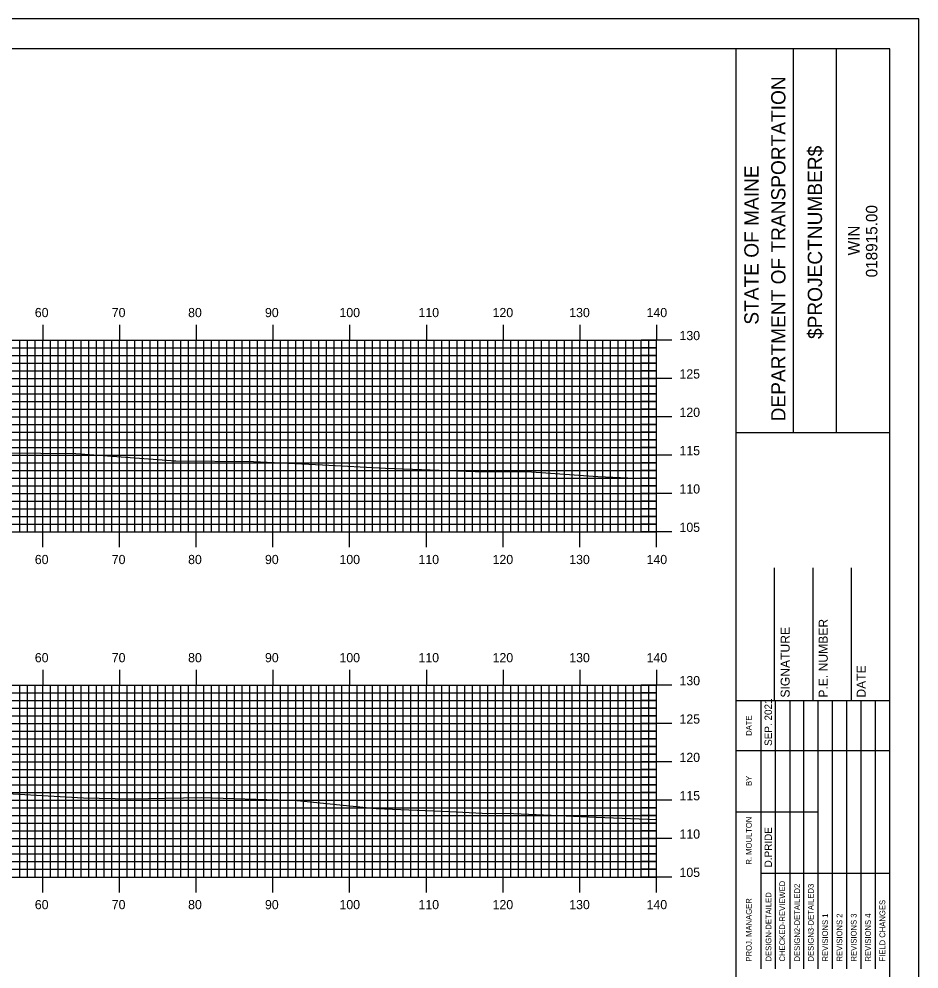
# Model space of a CAD drawing. Extents: x 1771629 to 1771972, y 442591 to 442811.
# Drawn here: x 1771851.5 to 1771968.8, y 442686.7 to 442810.5 of the extents above; entities that cross this region are included whole.
import ezdxf

# ---------------------------------------------------------------- set-up
doc = ezdxf.new("R2010")
doc.units = 0
for name, color, linetype in [('BORDER', 7, 'Continuous'), ('H_V ANNOTATION', 7, 'Continuous'), ('MAJOR', 7, 'Continuous'), ('MINOR', 7, 'Continuous'), ('PLOT BOUNDARY', 7, 'Continuous'), ('S_Roadway_Centerline', 7, 'Continuous')]:
    doc.layers.add(name, color=color, linetype=linetype)

msp = doc.modelspace()

# ---------------------------------------------------------------- linework, layer by layer
at = {"layer": 'BORDER'}
for p, q in [((1771944.98, 442596.67), (1771944.98, 442806.67)), ((1771952.44, 442756.66), (1771952.44, 442806.66)), ((1771958.03, 442756.66), (1771958.03, 442806.66)), ((1771944.98, 442756.65), (1771964.98, 442756.65)), ((1771949.98, 442721.67), (1771949.98, 442738.97)), ((1771954.98, 442721.67), (1771954.98, 442738.97)), ((1771959.98, 442721.67), (1771959.98, 442738.97)), ((1771944.98, 442721.67), (1771964.98, 442721.67))]:
    msp.add_line(p, q, dxfattribs=at)
msp.add_lwpolyline([(1771644.98, 442596.67), (1771964.98, 442596.67), (1771964.98, 442806.67), (1771644.98, 442806.67)], close=True, dxfattribs=at)
for points in [[(1771948.21, 442715.17), (1771948.21, 442721.67)], [(1771950.08, 442686.68), (1771950.08, 442721.67)], [(1771951.94, 442721.67), (1771951.94, 442686.68)], [(1771953.8, 442686.68), (1771953.8, 442721.67)], [(1771955.67, 442686.68), (1771955.67, 442721.67)], [(1771957.53, 442686.68), (1771957.53, 442721.67)], [(1771959.39, 442686.68), (1771959.39, 442721.67)], [(1771961.26, 442686.68), (1771961.26, 442721.67)], [(1771963.12, 442686.68), (1771963.12, 442721.67)], [(1771948.21, 442686.68), (1771948.21, 442720.26)], [(1771944.98, 442715.17), (1771964.98, 442715.17)], [(1771944.98, 442707.17), (1771948.21, 442707.17)], [(1771948.21, 442707.17), (1771955.66, 442707.17)], [(1771948.21, 442699.17), (1771964.98, 442699.17)]]:
    msp.add_lwpolyline(points, dxfattribs=at)
at = {"layer": 'MAJOR'}
for p, q in [((1771854.58, 442770.67), (1771854.58, 442768.67)), ((1771864.58, 442770.67), (1771864.58, 442768.67)), ((1771874.58, 442770.67), (1771874.58, 442768.67)), ((1771884.58, 442770.67), (1771884.58, 442768.67)), ((1771894.58, 442770.67), (1771894.58, 442768.67)), ((1771904.58, 442770.67), (1771904.58, 442768.67)), ((1771914.58, 442770.67), (1771914.58, 442768.67)), ((1771924.58, 442770.67), (1771924.58, 442768.67)), ((1771934.58, 442770.67), (1771934.58, 442768.67)), ((1771654.58, 442768.67), (1771934.58, 442768.67)), ((1771654.58, 442768.67), (1771934.58, 442768.67)), ((1771854.58, 442743.67), (1771854.58, 442768.67)), ((1771864.58, 442743.67), (1771864.58, 442768.67)), ((1771874.58, 442743.67), (1771874.58, 442768.67)), ((1771884.58, 442743.67), (1771884.58, 442768.67)), ((1771894.58, 442743.67), (1771894.58, 442768.67)), ((1771904.58, 442743.67), (1771904.58, 442768.67)), ((1771914.58, 442743.67), (1771914.58, 442768.67)), ((1771924.58, 442743.67), (1771924.58, 442768.67)), ((1771936.58, 442768.67), (1771932.58, 442768.67)), ((1771934.58, 442743.67), (1771934.58, 442768.67)), ((1771934.58, 442743.67), (1771934.58, 442768.67)), ((1771654.58, 442763.67), (1771934.58, 442763.67)), ((1771936.58, 442763.67), (1771932.58, 442763.67)), ((1771654.58, 442758.67), (1771934.58, 442758.67)), ((1771936.58, 442758.67), (1771932.58, 442758.67)), ((1771654.58, 442753.67), (1771934.58, 442753.67)), ((1771936.58, 442753.67), (1771932.58, 442753.67)), ((1771654.58, 442748.67), (1771934.58, 442748.67)), ((1771936.58, 442748.67), (1771932.58, 442748.67)), ((1771654.58, 442743.67), (1771934.58, 442743.67)), ((1771654.58, 442743.67), (1771934.58, 442743.67)), ((1771854.58, 442741.66), (1771854.58, 442743.67)), ((1771864.58, 442741.66), (1771864.58, 442743.67)), ((1771874.58, 442741.66), (1771874.58, 442743.67)), ((1771884.58, 442741.66), (1771884.58, 442743.67)), ((1771894.58, 442741.66), (1771894.58, 442743.67)), ((1771904.58, 442741.66), (1771904.58, 442743.67)), ((1771914.58, 442741.66), (1771914.58, 442743.67)), ((1771924.58, 442741.66), (1771924.58, 442743.67)), ((1771936.58, 442743.67), (1771932.58, 442743.67)), ((1771934.58, 442741.66), (1771934.58, 442743.67)), ((1771854.58, 442725.67), (1771854.58, 442723.67)), ((1771864.58, 442725.67), (1771864.58, 442723.67)), ((1771874.58, 442725.67), (1771874.58, 442723.67)), ((1771884.58, 442725.67), (1771884.58, 442723.67)), ((1771894.58, 442725.67), (1771894.58, 442723.67)), ((1771904.58, 442725.67), (1771904.58, 442723.67)), ((1771914.58, 442725.67), (1771914.58, 442723.67)), ((1771924.58, 442725.67), (1771924.58, 442723.67)), ((1771934.58, 442725.67), (1771934.58, 442723.67)), ((1771654.58, 442723.67), (1771934.58, 442723.67)), ((1771654.58, 442723.67), (1771934.58, 442723.67)), ((1771854.58, 442698.67), (1771854.58, 442723.67)), ((1771864.58, 442698.67), (1771864.58, 442723.67)), ((1771874.58, 442698.67), (1771874.58, 442723.67)), ((1771884.58, 442698.67), (1771884.58, 442723.67)), ((1771894.58, 442698.67), (1771894.58, 442723.67)), ((1771904.58, 442698.67), (1771904.58, 442723.67)), ((1771914.58, 442698.67), (1771914.58, 442723.67)), ((1771924.58, 442698.67), (1771924.58, 442723.67)), ((1771936.58, 442723.67), (1771932.58, 442723.67)), ((1771934.58, 442698.67), (1771934.58, 442723.67)), ((1771934.58, 442698.67), (1771934.58, 442723.67)), ((1771654.58, 442718.67), (1771934.58, 442718.67)), ((1771936.58, 442718.67), (1771932.58, 442718.67)), ((1771654.58, 442713.67), (1771934.58, 442713.67)), ((1771936.58, 442713.67), (1771932.58, 442713.67)), ((1771654.58, 442708.67), (1771934.58, 442708.67)), ((1771936.58, 442708.67), (1771932.58, 442708.67)), ((1771654.58, 442703.67), (1771934.58, 442703.67)), ((1771936.58, 442703.67), (1771932.58, 442703.67)), ((1771654.58, 442698.67), (1771934.58, 442698.67)), ((1771654.58, 442698.67), (1771934.58, 442698.67)), ((1771854.58, 442696.66), (1771854.58, 442698.67)), ((1771864.58, 442696.66), (1771864.58, 442698.67)), ((1771874.58, 442696.66), (1771874.58, 442698.67)), ((1771884.58, 442696.66), (1771884.58, 442698.67)), ((1771894.58, 442696.66), (1771894.58, 442698.67)), ((1771904.58, 442696.66), (1771904.58, 442698.67)), ((1771914.58, 442696.66), (1771914.58, 442698.67)), ((1771924.58, 442696.66), (1771924.58, 442698.67)), ((1771936.58, 442698.67), (1771932.58, 442698.67)), ((1771934.58, 442696.66), (1771934.58, 442698.67))]:
    msp.add_line(p, q, dxfattribs=at)
at = {"layer": 'MINOR'}
for p, q in [((1771851.58, 442743.67), (1771851.58, 442768.67)), ((1771852.58, 442743.67), (1771852.58, 442768.67)), ((1771853.58, 442743.67), (1771853.58, 442768.67)), ((1771855.58, 442743.67), (1771855.58, 442768.67)), ((1771856.58, 442743.67), (1771856.58, 442768.67)), ((1771857.58, 442743.67), (1771857.58, 442768.67)), ((1771858.58, 442743.67), (1771858.58, 442768.67)), ((1771859.58, 442743.67), (1771859.58, 442768.67)), ((1771860.58, 442743.67), (1771860.58, 442768.67)), ((1771861.58, 442743.67), (1771861.58, 442768.67)), ((1771862.58, 442743.67), (1771862.58, 442768.67)), ((1771863.58, 442743.67), (1771863.58, 442768.67)), ((1771865.58, 442743.67), (1771865.58, 442768.67)), ((1771866.58, 442743.67), (1771866.58, 442768.67)), ((1771867.58, 442743.67), (1771867.58, 442768.67)), ((1771868.58, 442743.67), (1771868.58, 442768.67)), ((1771869.58, 442743.67), (1771869.58, 442768.67)), ((1771870.58, 442743.67), (1771870.58, 442768.67)), ((1771871.58, 442743.67), (1771871.58, 442768.67)), ((1771872.58, 442743.67), (1771872.58, 442768.67)), ((1771873.58, 442743.67), (1771873.58, 442768.67)), ((1771875.58, 442743.67), (1771875.58, 442768.67)), ((1771876.58, 442743.67), (1771876.58, 442768.67)), ((1771877.58, 442743.67), (1771877.58, 442768.67)), ((1771878.58, 442743.67), (1771878.58, 442768.67)), ((1771879.58, 442743.67), (1771879.58, 442768.67)), ((1771880.58, 442743.67), (1771880.58, 442768.67)), ((1771881.58, 442743.67), (1771881.58, 442768.67)), ((1771882.58, 442743.67), (1771882.58, 442768.67)), ((1771883.58, 442743.67), (1771883.58, 442768.67)), ((1771885.58, 442743.67), (1771885.58, 442768.67)), ((1771886.58, 442743.67), (1771886.58, 442768.67)), ((1771887.58, 442743.67), (1771887.58, 442768.67)), ((1771888.58, 442743.67), (1771888.58, 442768.67)), ((1771889.58, 442743.67), (1771889.58, 442768.67)), ((1771890.58, 442743.67), (1771890.58, 442768.67)), ((1771891.58, 442743.67), (1771891.58, 442768.67)), ((1771892.58, 442743.67), (1771892.58, 442768.67)), ((1771893.58, 442743.67), (1771893.58, 442768.67)), ((1771895.58, 442743.67), (1771895.58, 442768.67)), ((1771896.58, 442743.67), (1771896.58, 442768.67)), ((1771897.58, 442743.67), (1771897.58, 442768.67)), ((1771898.58, 442743.67), (1771898.58, 442768.67)), ((1771899.58, 442743.67), (1771899.58, 442768.67)), ((1771900.58, 442743.67), (1771900.58, 442768.67)), ((1771901.58, 442743.67), (1771901.58, 442768.67)), ((1771902.58, 442743.67), (1771902.58, 442768.67)), ((1771903.58, 442743.67), (1771903.58, 442768.67)), ((1771905.58, 442743.67), (1771905.58, 442768.67)), ((1771906.58, 442743.67), (1771906.58, 442768.67)), ((1771907.58, 442743.67), (1771907.58, 442768.67)), ((1771908.58, 442743.67), (1771908.58, 442768.67)), ((1771909.58, 442743.67), (1771909.58, 442768.67)), ((1771910.58, 442743.67), (1771910.58, 442768.67)), ((1771911.58, 442743.67), (1771911.58, 442768.67)), ((1771912.58, 442743.67), (1771912.58, 442768.67)), ((1771913.58, 442743.67), (1771913.58, 442768.67)), ((1771915.58, 442743.67), (1771915.58, 442768.67)), ((1771916.58, 442743.67), (1771916.58, 442768.67)), ((1771917.58, 442743.67), (1771917.58, 442768.67)), ((1771918.58, 442743.67), (1771918.58, 442768.67)), ((1771919.58, 442743.67), (1771919.58, 442768.67)), ((1771920.58, 442743.67), (1771920.58, 442768.67)), ((1771921.58, 442743.67), (1771921.58, 442768.67)), ((1771922.58, 442743.67), (1771922.58, 442768.67)), ((1771923.58, 442743.67), (1771923.58, 442768.67)), ((1771925.58, 442743.67), (1771925.58, 442768.67)), ((1771926.58, 442743.67), (1771926.58, 442768.67)), ((1771927.58, 442743.67), (1771927.58, 442768.67)), ((1771928.58, 442743.67), (1771928.58, 442768.67)), ((1771929.58, 442743.67), (1771929.58, 442768.67)), ((1771930.58, 442743.67), (1771930.58, 442768.67)), ((1771931.58, 442743.67), (1771931.58, 442768.67)), ((1771932.58, 442743.67), (1771932.58, 442768.67)), ((1771933.58, 442743.67), (1771933.58, 442768.67)), ((1771654.58, 442767.67), (1771934.58, 442767.67)), ((1771934.58, 442767.67), (1771932.58, 442767.67)), ((1771654.58, 442766.67), (1771934.58, 442766.67)), ((1771934.58, 442766.67), (1771932.58, 442766.67)), ((1771654.58, 442765.67), (1771934.58, 442765.67)), ((1771934.58, 442765.67), (1771932.58, 442765.67)), ((1771654.58, 442764.67), (1771934.58, 442764.67)), ((1771934.58, 442764.67), (1771932.58, 442764.67)), ((1771654.58, 442762.67), (1771934.58, 442762.67)), ((1771934.58, 442762.67), (1771932.58, 442762.67)), ((1771654.58, 442761.67), (1771934.58, 442761.67)), ((1771934.58, 442761.67), (1771932.58, 442761.67)), ((1771654.58, 442760.67), (1771934.58, 442760.67)), ((1771934.58, 442760.67), (1771932.58, 442760.67)), ((1771654.58, 442759.67), (1771934.58, 442759.67)), ((1771934.58, 442759.67), (1771932.58, 442759.67)), ((1771654.58, 442757.67), (1771934.58, 442757.67)), ((1771934.58, 442757.67), (1771932.58, 442757.67)), ((1771654.58, 442756.67), (1771934.58, 442756.67)), ((1771934.58, 442756.67), (1771932.58, 442756.67)), ((1771654.58, 442755.67), (1771934.58, 442755.67)), ((1771934.58, 442755.67), (1771932.58, 442755.67)), ((1771654.58, 442754.67), (1771934.58, 442754.67)), ((1771934.58, 442754.67), (1771932.58, 442754.67)), ((1771654.58, 442752.67), (1771934.58, 442752.67)), ((1771934.58, 442752.67), (1771932.58, 442752.67)), ((1771654.58, 442751.67), (1771934.58, 442751.67)), ((1771934.58, 442751.67), (1771932.58, 442751.67)), ((1771654.58, 442750.67), (1771934.58, 442750.67)), ((1771934.58, 442750.67), (1771932.58, 442750.67)), ((1771654.58, 442749.67), (1771934.58, 442749.67)), ((1771934.58, 442749.67), (1771932.58, 442749.67)), ((1771654.58, 442747.67), (1771934.58, 442747.67)), ((1771934.58, 442747.67), (1771932.58, 442747.67)), ((1771654.58, 442746.67), (1771934.58, 442746.67)), ((1771934.58, 442746.67), (1771932.58, 442746.67)), ((1771654.58, 442745.67), (1771934.58, 442745.67)), ((1771934.58, 442745.67), (1771932.58, 442745.67)), ((1771654.58, 442744.67), (1771934.58, 442744.67)), ((1771934.58, 442744.67), (1771932.58, 442744.67)), ((1771851.58, 442698.67), (1771851.58, 442723.67)), ((1771852.58, 442698.67), (1771852.58, 442723.67)), ((1771853.58, 442698.67), (1771853.58, 442723.67)), ((1771855.58, 442698.67), (1771855.58, 442723.67)), ((1771856.58, 442698.67), (1771856.58, 442723.67)), ((1771857.58, 442698.67), (1771857.58, 442723.67)), ((1771858.58, 442698.67), (1771858.58, 442723.67)), ((1771859.58, 442698.67), (1771859.58, 442723.67)), ((1771860.58, 442698.67), (1771860.58, 442723.67)), ((1771861.58, 442698.67), (1771861.58, 442723.67)), ((1771862.58, 442698.67), (1771862.58, 442723.67)), ((1771863.58, 442698.67), (1771863.58, 442723.67)), ((1771865.58, 442698.67), (1771865.58, 442723.67)), ((1771866.58, 442698.67), (1771866.58, 442723.67)), ((1771867.58, 442698.67), (1771867.58, 442723.67)), ((1771868.58, 442698.67), (1771868.58, 442723.67)), ((1771869.58, 442698.67), (1771869.58, 442723.67)), ((1771870.58, 442698.67), (1771870.58, 442723.67)), ((1771871.58, 442698.67), (1771871.58, 442723.67)), ((1771872.58, 442698.67), (1771872.58, 442723.67)), ((1771873.58, 442698.67), (1771873.58, 442723.67)), ((1771875.58, 442698.67), (1771875.58, 442723.67)), ((1771876.58, 442698.67), (1771876.58, 442723.67)), ((1771877.58, 442698.67), (1771877.58, 442723.67)), ((1771878.58, 442698.67), (1771878.58, 442723.67)), ((1771879.58, 442698.67), (1771879.58, 442723.67)), ((1771880.58, 442698.67), (1771880.58, 442723.67)), ((1771881.58, 442698.67), (1771881.58, 442723.67)), ((1771882.58, 442698.67), (1771882.58, 442723.67)), ((1771883.58, 442698.67), (1771883.58, 442723.67)), ((1771885.58, 442698.67), (1771885.58, 442723.67)), ((1771886.58, 442698.67), (1771886.58, 442723.67)), ((1771887.58, 442698.67), (1771887.58, 442723.67)), ((1771888.58, 442698.67), (1771888.58, 442723.67)), ((1771889.58, 442698.67), (1771889.58, 442723.67)), ((1771890.58, 442698.67), (1771890.58, 442723.67)), ((1771891.58, 442698.67), (1771891.58, 442723.67)), ((1771892.58, 442698.67), (1771892.58, 442723.67)), ((1771893.58, 442698.67), (1771893.58, 442723.67)), ((1771895.58, 442698.67), (1771895.58, 442723.67)), ((1771896.58, 442698.67), (1771896.58, 442723.67)), ((1771897.58, 442698.67), (1771897.58, 442723.67)), ((1771898.58, 442698.67), (1771898.58, 442723.67)), ((1771899.58, 442698.67), (1771899.58, 442723.67)), ((1771900.58, 442698.67), (1771900.58, 442723.67)), ((1771901.58, 442698.67), (1771901.58, 442723.67)), ((1771902.58, 442698.67), (1771902.58, 442723.67)), ((1771903.58, 442698.67), (1771903.58, 442723.67)), ((1771905.58, 442698.67), (1771905.58, 442723.67)), ((1771906.58, 442698.67), (1771906.58, 442723.67)), ((1771907.58, 442698.67), (1771907.58, 442723.67)), ((1771908.58, 442698.67), (1771908.58, 442723.67)), ((1771909.58, 442698.67), (1771909.58, 442723.67)), ((1771910.58, 442698.67), (1771910.58, 442723.67)), ((1771911.58, 442698.67), (1771911.58, 442723.67)), ((1771912.58, 442698.67), (1771912.58, 442723.67)), ((1771913.58, 442698.67), (1771913.58, 442723.67)), ((1771915.58, 442698.67), (1771915.58, 442723.67)), ((1771916.58, 442698.67), (1771916.58, 442723.67)), ((1771917.58, 442698.67), (1771917.58, 442723.67)), ((1771918.58, 442698.67), (1771918.58, 442723.67)), ((1771919.58, 442698.67), (1771919.58, 442723.67)), ((1771920.58, 442698.67), (1771920.58, 442723.67)), ((1771921.58, 442698.67), (1771921.58, 442723.67)), ((1771922.58, 442698.67), (1771922.58, 442723.67)), ((1771923.58, 442698.67), (1771923.58, 442723.67)), ((1771925.58, 442698.67), (1771925.58, 442723.67)), ((1771926.58, 442698.67), (1771926.58, 442723.67)), ((1771927.58, 442698.67), (1771927.58, 442723.67)), ((1771928.58, 442698.67), (1771928.58, 442723.67)), ((1771929.58, 442698.67), (1771929.58, 442723.67)), ((1771930.58, 442698.67), (1771930.58, 442723.67)), ((1771931.58, 442698.67), (1771931.58, 442723.67)), ((1771932.58, 442698.67), (1771932.58, 442723.67)), ((1771933.58, 442698.67), (1771933.58, 442723.67)), ((1771654.58, 442722.67), (1771934.58, 442722.67)), ((1771654.58, 442721.67), (1771934.58, 442721.67)), ((1771934.58, 442722.67), (1771932.58, 442722.67)), ((1771934.58, 442721.67), (1771932.58, 442721.67)), ((1771654.58, 442720.67), (1771934.58, 442720.67)), ((1771934.58, 442720.67), (1771932.58, 442720.67)), ((1771654.58, 442719.67), (1771934.58, 442719.67)), ((1771934.58, 442719.67), (1771932.58, 442719.67)), ((1771654.58, 442717.67), (1771934.58, 442717.67)), ((1771654.58, 442716.67), (1771934.58, 442716.67)), ((1771934.58, 442717.67), (1771932.58, 442717.67)), ((1771934.58, 442716.67), (1771932.58, 442716.67)), ((1771654.58, 442715.67), (1771934.58, 442715.67)), ((1771934.58, 442715.67), (1771932.58, 442715.67)), ((1771654.58, 442714.67), (1771934.58, 442714.67)), ((1771934.58, 442714.67), (1771932.58, 442714.67)), ((1771654.58, 442712.67), (1771934.58, 442712.67)), ((1771654.58, 442711.67), (1771934.58, 442711.67)), ((1771934.58, 442712.67), (1771932.58, 442712.67)), ((1771934.58, 442711.67), (1771932.58, 442711.67)), ((1771654.58, 442710.67), (1771934.58, 442710.67)), ((1771934.58, 442710.67), (1771932.58, 442710.67)), ((1771654.58, 442709.67), (1771934.58, 442709.67)), ((1771934.58, 442709.67), (1771932.58, 442709.67)), ((1771654.58, 442707.67), (1771934.58, 442707.67)), ((1771654.58, 442706.67), (1771934.58, 442706.67)), ((1771934.58, 442707.67), (1771932.58, 442707.67)), ((1771934.58, 442706.67), (1771932.58, 442706.67)), ((1771654.58, 442705.67), (1771934.58, 442705.67)), ((1771934.58, 442705.67), (1771932.58, 442705.67)), ((1771654.58, 442704.67), (1771934.58, 442704.67)), ((1771934.58, 442704.67), (1771932.58, 442704.67)), ((1771654.58, 442702.67), (1771934.58, 442702.67)), ((1771654.58, 442701.67), (1771934.58, 442701.67)), ((1771934.58, 442702.67), (1771932.58, 442702.67)), ((1771934.58, 442701.67), (1771932.58, 442701.67)), ((1771654.58, 442700.67), (1771934.58, 442700.67)), ((1771934.58, 442700.67), (1771932.58, 442700.67)), ((1771654.58, 442699.67), (1771934.58, 442699.67)), ((1771934.58, 442699.67), (1771932.58, 442699.67))]:
    msp.add_line(p, q, dxfattribs=at)
at = {"layer": 'PLOT BOUNDARY'}
msp.add_lwpolyline([(1771628.79, 442590.55), (1771968.79, 442590.55), (1771968.79, 442810.55), (1771628.79, 442810.55)], close=True, dxfattribs=at)
at = {"layer": 'S_Roadway_Centerline'}
for points in [[(1771849.75, 442753.96), (1771858.91, 442753.91), (1771871.32, 442752.96), (1771871.59, 442752.94), (1771871.92, 442752.93), (1771882.07, 442752.84), (1771891.04, 442752.42), (1771899.26, 442751.96), (1771910.93, 442751.54), (1771918.3, 442751.52), (1771926.95, 442750.89), (1771931.84, 442750.67), (1771934.58, 442750.61)], [(1771846.07, 442709.78), (1771859.88, 442709), (1771866.07, 442708.87), (1771875.24, 442709.02), (1771886.66, 442708.71), (1771887.33, 442708.67), (1771898.02, 442707.62), (1771907.63, 442707.2), (1771911.87, 442707.01), (1771915.92, 442706.95), (1771926.71, 442706.46), (1771934.58, 442706.18)]]:
    msp.add_lwpolyline(points, dxfattribs=at)

# ---------------------------------------------------------------- texts
at = {"layer": 'BORDER'}
for s, height, p in [('DEPARTMENT OF TRANSPORTATION', 1.8635, (1771951.39, 442758.08)), ('$PROJECTNUMBER$', 1.8635, (1771956.16, 442768.82)), ('STATE OF MAINE', 1.8635, (1771947.89, 442770.69)), ('018915.00', 1.491, (1771963.37, 442776.86)), ('WIN', 1.491, (1771961.05, 442779.73)), ('P.E. NUMBER', 1.1811, (1771956.9, 442722.06)), ('SIGNATURE', 1.181, (1771951.94, 442722.06)), ('DATE', 1.181, (1771961.86, 442722.06)), ('SEP. 2021', 0.969, (1771949.63, 442715.76)), ('DATE', 0.743, (1771946.99, 442717.08)), ('BY', 0.743, (1771946.99, 442710.54)), ('R. MOULTON', 0.745, (1771946.99, 442700.28)), ('D.PRIDE', 0.969, (1771949.63, 442699.92)), ('CHECKED-REVIEWED', 0.7455, (1771951.34, 442687.65)), ('DESIGN2-DETAILED2', 0.7455, (1771953.28, 442687.65)), ('DESIGN3-DETAILED3', 0.7455, (1771955.07, 442687.65)), ('PROJ. MANAGER', 0.7455, (1771946.99, 442687.65)), ('DESIGN-DETAILED', 0.7455, (1771949.55, 442687.65)), ('FIELD CHANGES', 0.7455, (1771964.39, 442687.65)), ('REVISIONS 1', 0.7455, (1771956.93, 442687.65)), ('REVISIONS 2', 0.7455, (1771958.8, 442687.65)), ('REVISIONS 3', 0.7455, (1771960.66, 442687.65)), ('REVISIONS 4', 0.7455, (1771962.52, 442687.65))]:
    msp.add_text(s, height=height, rotation=90, dxfattribs=at).set_placement(p)
at = {"layer": 'H_V ANNOTATION'}
for s, p in [('60', (1771853.55, 442771.67)), ('70', (1771863.58, 442771.67)), ('80', (1771873.53, 442771.67)), ('90', (1771883.55, 442771.67)), ('100', (1771893.26, 442771.67)), ('110', (1771903.56, 442771.67)), ('120', (1771913.22, 442771.67)), ('130', (1771923.21, 442771.67)), ('140', (1771933.29, 442771.67)), ('130', (1771937.58, 442768.67)), ('125', (1771937.58, 442763.67)), ('120', (1771937.58, 442758.67)), ('115', (1771937.58, 442753.67)), ('110', (1771937.58, 442748.67)), ('105', (1771937.58, 442743.67)), ('60', (1771853.55, 442739.47)), ('70', (1771863.58, 442739.47)), ('80', (1771873.53, 442739.47)), ('90', (1771883.55, 442739.47)), ('100', (1771893.26, 442739.47)), ('110', (1771903.56, 442739.47)), ('120', (1771913.22, 442739.47)), ('130', (1771923.21, 442739.47)), ('140', (1771933.29, 442739.47)), ('60', (1771853.55, 442726.67)), ('70', (1771863.58, 442726.67)), ('80', (1771873.53, 442726.67)), ('90', (1771883.55, 442726.67)), ('100', (1771893.26, 442726.67)), ('110', (1771903.56, 442726.67)), ('120', (1771913.22, 442726.67)), ('130', (1771923.21, 442726.67)), ('140', (1771933.29, 442726.67)), ('130', (1771937.58, 442723.67)), ('125', (1771937.58, 442718.67)), ('120', (1771937.58, 442713.67)), ('115', (1771937.58, 442708.67)), ('110', (1771937.58, 442703.67)), ('105', (1771937.58, 442698.67)), ('60', (1771853.55, 442694.47)), ('70', (1771863.58, 442694.47)), ('80', (1771873.53, 442694.47)), ('90', (1771883.55, 442694.47)), ('100', (1771893.26, 442694.47)), ('110', (1771903.56, 442694.47)), ('120', (1771913.22, 442694.47)), ('130', (1771923.21, 442694.47)), ('140', (1771933.29, 442694.47))]:
    msp.add_text(s, height=1.2, dxfattribs=at).set_placement(p)

doc.saveas('drawing.dxf')
